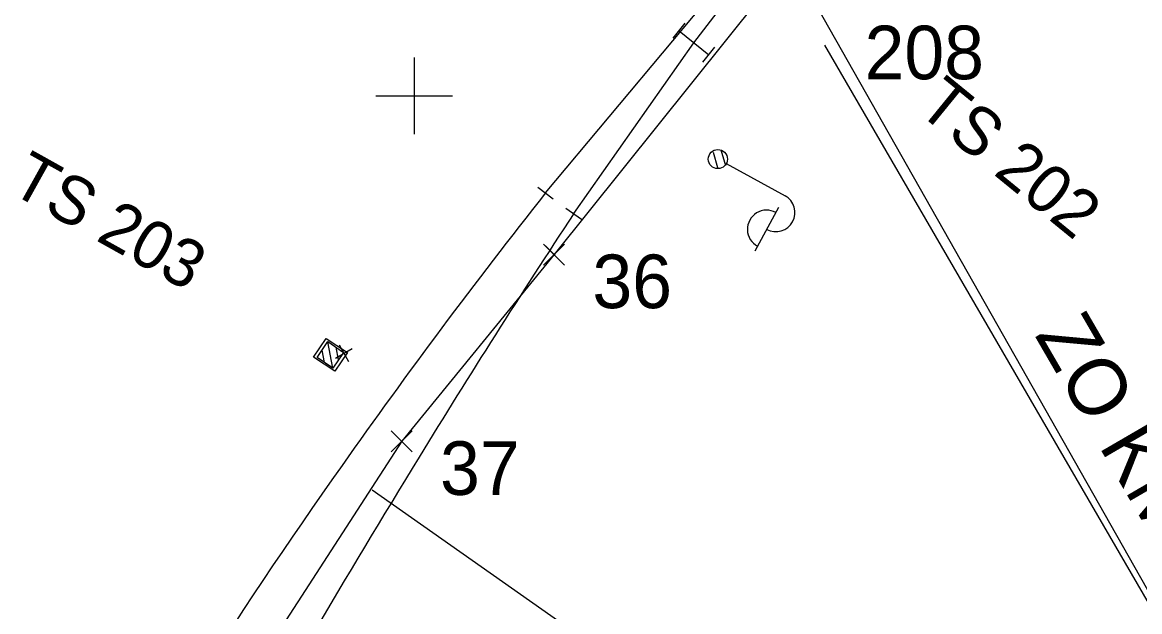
# Model space of a CAD drawing. Extents: x -566182 to -565305, y -1203073 to -1202401.
# Drawn here: x -565820.5 to -565762, y -1202826.9 to -1202796.2 of the extents above; entities that cross this region are included whole.
import ezdxf

# ---------------------------------------------------------------- set-up
doc = ezdxf.new("R2010")
doc.units = 0
for name, color, linetype in [('CD', 7, 'Continuous'), ('SZDC', 7, 'Continuous'), ('Vrstva 1', 7, 'Continuous'), ('Vrstva 10', 7, 'Continuous'), ('Vrstva 12', 7, 'Continuous'), ('Vrstva 13', 7, 'Continuous'), ('Vrstva 18', 7, 'Continuous'), ('Vrstva 39', 7, 'Continuous'), ('Vrstva 5', 7, 'Continuous'), ('Vrstva 6', 7, 'Continuous'), ('Vrstva 60', 7, 'Continuous'), ('Vrstva 8', 7, 'Continuous')]:
    doc.layers.add(name, color=color, linetype=linetype)

# ---------------------------------------------------------------- blocks, each defined once
blk = doc.blocks.new('C84')
at = {"layer": 'Vrstva 8'}
blk.add_line((0, 5), (0, -5), dxfattribs=at)
blk = doc.blocks.new('C649')
at = {"layer": 'Vrstva 18'}
for p, q in [((-5, 10), (5, 10)), ((0, 10), (0, -10)), ((-5, -10), (5, -10))]:
    blk.add_line(p, q, dxfattribs=at)
blk = doc.blocks.new('C691')
at = {"layer": 'Vrstva 12'}
for p, q in [((-5, 0), (5, 0)), ((0, 5), (0, -5))]:
    blk.add_line(p, q, dxfattribs=at)
blk = doc.blocks.new('C669_4')
at = {"layer": 'Vrstva 6'}
for p, q in [((0, 4.99), (0, 40.01)), ((7.01, 40.01), (33.01, 40.01)), ((-5, -1), (1.01, 5)), ((-1.99, -3.99), (4.01, 2))]:
    blk.add_line(p, q, dxfattribs=at)
blk.add_circle((0, 0), 5, dxfattribs=at)
blk.add_circle((0, 0), 5, dxfattribs=at)
for centre, start, end in [((10.01, 40.01), 0.00015, 180.00015), ((20.01, 39.89), 179.29757, 0.70272)]:
    blk.add_arc(centre, 10, start, end, dxfattribs=at)
blk = doc.blocks.new('C661_4')
at = {"layer": 'Vrstva 12'}
for p, q in [((-5, 0.34), (-0.33, 5)), ((-5, -4.98), (4.97, 5)), ((0.26, -4.99), (4.99, -0.28))]:
    blk.add_line(p, q, dxfattribs=at)
blk.add_lwpolyline([(-5, 5.01), (5.01, 5), (5, -5.01), (-5.01, -5)], close=True, dxfattribs=at)
blk.add_lwpolyline([(-5, 5.01), (5.01, 5), (5, -5.01), (-5.01, -5), (-5, 5.01)], dxfattribs=at)

msp = doc.modelspace()

# ---------------------------------------------------------------- linework, layer by layer
at = {"layer": 'CD'}
msp.add_line((-565780.3, -1202792.87), (-565792.68, -1202808.29), dxfattribs=at)
at = {"layer": 'SZDC'}
for p, q in [((-565792.68, -1202808.29), (-565800.65, -1202818.05)), ((-565800.65, -1202818.05), (-565813.8, -1202838.35))]:
    msp.add_line(p, q, dxfattribs=at)
at = {"layer": 'Vrstva 1'}
msp.add_line((-565756.98, -1202834.009), (-565794.791, -1202767.359), dxfattribs=at)
at = {"layer": 'Vrstva 10'}
for p, q in [((-565805.262, -1202813.654), (-565804.593, -1202812.679)), ((-565804.593, -1202812.679), (-565803.489, -1202813.412)), ((-565804.15, -1202814.388), (-565805.262, -1202813.654)), ((-565803.489, -1202813.412), (-565804.15, -1202814.388))]:
    msp.add_line(p, q, dxfattribs=at)
at = {"layer": 'Vrstva 5'}
for p, q in [((-565800, -1202798), (-565800, -1202802)), ((-565802, -1202800), (-565798, -1202800))]:
    msp.add_line(p, q, dxfattribs=at)
at = {"layer": 'Vrstva 6'}
for centre, radius, start, end in [((-565548.709, -1202998.84), 311.903, 141.59251, 144.86094), ((-565407.592, -1203059.157), 459.905, 146.62419, 148.50335), ((-565363.773, -1203087.21), 511.926, 148.3884, 150.84714), ((-565601.105, -1202963.584), 248.767, 144.5555, 151.27118)]:
    msp.add_arc(centre, radius, start, end, dxfattribs=at)
at = {"layer": 'Vrstva 60'}
for p, q in [((-565778.529, -1202797.343), (-565746.957, -1202851.708)), ((-565792.23, -1202808.74), (-565793.23, -1202807.74)), ((-565792.23, -1202807.84), (-565793.23, -1202808.84)), ((-565793.13, -1202808.74), (-565792.13, -1202807.74)), ((-565793.13, -1202807.84), (-565792.13, -1202808.84)), ((-565792.68, -1202808.29), (-565792.68, -1202808.29)), ((-565800.2, -1202818.5), (-565801.2, -1202817.5)), ((-565800.2, -1202817.6), (-565801.2, -1202818.6)), ((-565801.1, -1202818.5), (-565800.1, -1202817.5)), ((-565801.1, -1202817.6), (-565800.1, -1202818.6)), ((-565800.65, -1202818.05), (-565800.65, -1202818.05)), ((-565802.193, -1202820.582), (-565772.306, -1202841.565))]:
    msp.add_line(p, q, dxfattribs=at)
at = {"layer": 'Vrstva 8'}
for points in [[(-565793.12, -1202805.07), (-565783.14, -1202793.13), (-565764.35, -1202773.53)], [(-565791.65, -1202806.15), (-565785.36, -1202797.22), (-565778.453, -1202788.241)]]:
    msp.add_lwpolyline(points, dxfattribs=at)

# ---------------------------------------------------------------- block references
at = {"layer": 'Vrstva 12'}
for name, p, xscale, yscale, rotation in [('C691', (-565803.675, -1202813.447), 0.09999990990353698, 0.09999990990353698, 30.000029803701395), ('C661_4', (-565804.385, -1202813.535), 0.1000002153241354, 0.1000002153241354, 55.89206118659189)]:
    msp.add_blockref(name, p, dxfattribs=dict(at, xscale=xscale, yscale=yscale, rotation=rotation))
at = {"layer": 'Vrstva 18', "xscale": 0.09999994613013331, "yscale": 0.09999994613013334, "rotation": 51.02822249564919}
msp.add_blockref('C649', (-565785.36, -1202797.22), dxfattribs=at)
at = {"layer": 'Vrstva 6', "xscale": 0.10000009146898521, "yscale": 0.10000009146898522, "rotation": -118.58899600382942}
msp.add_blockref('C669_4', (-565784.108, -1202803.301), dxfattribs=at)
at = {"layer": 'Vrstva 8'}
for p, xscale, yscale, rotation in [((-565793.12, -1202805.07), 0.09999977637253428, 0.09999977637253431, 53.19061381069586), ((-565791.65, -1202806.15), 0.1000001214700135, 0.1000001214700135, 54.969554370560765)]:
    msp.add_blockref('C84', p, dxfattribs=dict(at, xscale=xscale, yscale=yscale, rotation=rotation))

# ---------------------------------------------------------------- texts
at = {"layer": 'Vrstva 13'}
for s, rotation, p in [('TS 202', 320.78159, (-565773.775, -1202800.775)), ('TS 203', 330.85049, (-565821.251, -1202804.983))]:
    msp.add_text(s, height=2.5, rotation=rotation, dxfattribs=at).set_placement(p)
at = {"layer": 'Vrstva 39'}
msp.add_text('ZO KM 103.069977', height=3, rotation=300.145, dxfattribs=at).set_placement((-565767.566, -1202812.492))
at = {"layer": 'Vrstva 60'}
for s, p in [('208', (-565776.433, -1202799.128)), ('36', (-565790.672, -1202811.09)), ('37', (-565798.642, -1202820.85))]:
    msp.add_text(s, height=2.8, dxfattribs=at).set_placement(p)

doc.saveas('drawing.dxf')
